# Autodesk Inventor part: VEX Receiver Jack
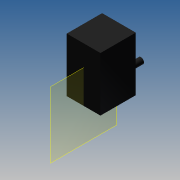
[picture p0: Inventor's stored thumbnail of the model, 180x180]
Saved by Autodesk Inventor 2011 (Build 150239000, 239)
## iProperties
Created: 2007-08
Part Number: VEX Receiver Jack
Material: ABS Plastic
Document SubType Name: Modeling
Designer: Tyler
Density: 1.06 g/cm^3
Author: Tyler
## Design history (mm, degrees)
feature "Base1"
workplane "Work Plane1"
body "Solid1"
